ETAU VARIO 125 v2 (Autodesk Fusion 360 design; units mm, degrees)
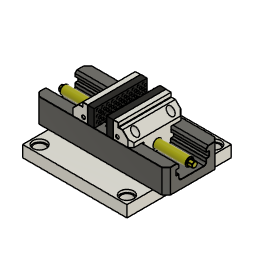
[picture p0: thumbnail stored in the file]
parameter "d42" = 0
parameter "d43" = 0
parameter "d44" = 0
parameter "d47" = 0
base_feature "Base Feature1" OffsetX 0 OffsetY 0 OffsetZ 0 OffsetX 0 OffsetY 0 OffsetZ 0 OffsetX 0 OffsetY 0 OffsetZ 0 OffsetX 0 OffsetY 0 OffsetZ 0
base_feature "Base Feature1" OffsetX 0 OffsetY 0 OffsetZ 0 OffsetX 0 OffsetY 0 OffsetZ 0 OffsetX 0 OffsetY 0 OffsetZ 0 OffsetX 0 OffsetY 0 OffsetZ 0
work_plane "WorkPlane2" User Parameter 30 named "Ouverture"
base_feature "Base Feature1"
position "Position1"
sketch "Sketch1" plane through (9.1729, 31.8972, 315) normal (1, 0, 0) x axis (0, 1, 0)
work_axis "WorkAxis1"
work_point "WorkPoint1"
joint_origin "JointOrigin7" OffsetX 0 OffsetY 0 OffsetZ 0
work_point "WorkPoint2"
work_point "WorkPoint1"
position "Position2"
position "Position3"
joint_origin "JointOrigin8" OffsetX 0 OffsetY 0 OffsetZ 0
joint_origin "JointOrigin3" OffsetX 0 OffsetY 0 OffsetZ 0
position "Position4"
ground "Terre5"
position "Position5"
ground "Terre6"
joint "Assembler5" alignOffsetX 0 alignOffsetY 0 alignOffsetZ 0
joint "Assembler6" alignOffsetX 0 alignOffsetY 0 alignOffsetZ 0
position "Position6" TranslateAlongZ -15 (= "-Ouverture / 2") TranslateAlongZ 15 (= "Ouverture / 2")
as_built_joint "Réelle"
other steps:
create_component "CreateComponent1"
create_component "CreateComponent1"
create_component "CreateComponent2"
create_component "CreateComponent2"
